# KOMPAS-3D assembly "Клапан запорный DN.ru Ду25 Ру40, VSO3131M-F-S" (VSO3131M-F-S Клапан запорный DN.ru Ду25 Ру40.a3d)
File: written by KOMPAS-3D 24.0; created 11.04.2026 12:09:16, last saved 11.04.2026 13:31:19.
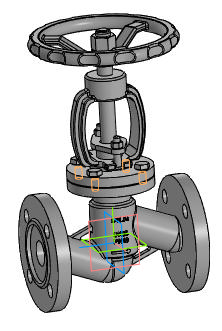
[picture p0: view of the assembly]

Document properties: Автор: R2D2; Полное имя файла: E:\Работа\Зайцев\VSO3131M-F-S Клапан запорный DN.ru Ду15-100 Ру40\DN25\исходные материалы\VSO3131M-F-S Клапан запорный DN.ru Ду25 Ру40.a3d

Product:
- Component [detail]: Корпус  | qty 1  | pos. 1  | Масса: 6.9; Автор: R2D2; source file: Корпус.m3d
- Component [detail]: Сборка  | qty 1  | pos. 2  | Масса: 1.450691; Автор: R2D2; source file: 2.m3d
- Component [standard]: Hexagon head screw ISO 4017 - М8 x 16  | qty 4  | Масса: 0.012085; Раздел спецификации: Стандартные изделия; Рассекать на разрезах: no
- Part/product: Клапан запорный DN.ru Ду25 Ру40  | designation VSO3131M-F-S
    Масса: 5.85
    Раздел спецификации: Прочие изделия
    Примечание: D090-02139

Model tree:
1. Массив по концентрической сетке:1  (with: Грань.Элемент вращения:2, Грань.Операция без истории:1)  (labels: Грань.Элемент выдавливания:9.Экземпляр ( 1, 3 ))  (4 pattern instances)
     Шаг 2 = 360

Referenced files in E:\Работа\Зайцев\VSO3131M-F-S Клапан запорный DN.ru Ду15-100 Ру40\DN25\исходные материалы\: Корпус.m3d, 2.m3d
Referenced files in C:\Program Files\ASCON\KOMPAS-3D v24\Libs\PolynomLib\DATA\vault\Methods\Kompas\3D\: PLib_Bolt_1_ISO_1100.m3d
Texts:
  Hexagon head screw
  BOSimple***PART:17775d1c-e7de-f283-40f0-d40789f7f59e***SHORTLOC:A259_7B16EF33AB1642D2[13;1,25;16;8;-;Undefined]
  Программные изделия  и базы данных
  VSO3131M-F-S
  Hexagon head screw ISO 4017 - М8 x 16 (1)
  hole1
  hole2
  Ось Z.Начало координат
  Ось Y.Начало координат
  Плоскость XY.Начало координат
  Плоскость ZY.Начало координат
